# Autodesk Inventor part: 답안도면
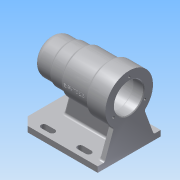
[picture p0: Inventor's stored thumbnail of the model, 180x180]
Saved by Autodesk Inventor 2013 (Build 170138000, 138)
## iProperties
Created: 2017-09
Part Number: 답안도면
Material: 알루미늄 6061
Document SubType Name: Modeling
Designer: Administrator
Density: 2.71 g/cm^3
Mass: 698.012 g
Surface Area: 708.878 cm^2
Volume: 257.569 cm^3
Author: Administrator
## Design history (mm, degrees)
sketch "스케치1"
  geometry: L1 (-56, 0)-(56, 0); L2 (-56, 0)-(-56, 25); L3 (-56, 25)-(-31, 25); L4 (-31, 25)-(-31, 27); L5 (-31, 27)-(-11, 27); L6 (-11, 27)-(-11, 30); L7 (-11, 30)-(28, 30); L8 (28, 30)-(28, 34); L9 (28, 34)-(56, 34); L10 (56, 34)-(56, 21); L11 (56, 21)-(41, 21); L12 (41, 21)-(41, 21); L13 (-13, 21)-(-13, 21); L14 (-13, 21)-(-24.7, 21); L15 (-25, 20.7)-(-25, 17.5); L16 (-25, 17.5)-(-42.7, 17.5); L17 (-43, 17.2)-(-43, 16); L18 (-43, 16)-(-46.7, 16); L19 (-47, 15.7)-(-47, 10.5); L20 (-47, 10.5)-(-47, 10.5); L21 (-50, 7.5)-(-50, 0); L22 (-10, 24)-(38, 24); A1 r 0.3 centre (-46.7, 15.7) between (-46.7, 16) and (-47, 15.7); A2 r 0.3 centre (-42.7, 17.2) between (-42.7, 17.5) and (-43, 17.2); A3 r 0.3 centre (-24.7, 20.7) between (-24.7, 21) and (-25, 20.7); A4 r 3 centre (-10, 21) between (-10, 24) and (-13, 21); A5 r 3 centre (38, 21) between (41, 21) and (38, 24); A6 r 3 centre (-47, 7.5) between (-47, 10.5) and (-50, 7.5); 7 further points
  constraints: 44 end point, 13 parallel, 13 point on line, 12 point on circle, 12 tangent, 6 centre point, 6 perpendicular, 4 equal radius, 1 horizontal, 1 midpoint, 1 vertical alignment
  dimensions: "d0" = 56 distance of L1.start point (0, 0); "d1" = 112 distance of L1.start L1.end; "d2" = 50 diameter of L3 L1; "d3" = 54 diameter of L5 L1; "d4" = 60 diameter of L7 L1; "d5" = 21 diameter of L20 L1; "d6" = 32 diameter of L18 L1; "d7" = 68 diameter of L9 L1; "d8" = 35 diameter of L16 L1; "d9" = 42 diameter of L14 L1; "d10" = 48 diameter of L22 L1; "d11" = 42 diameter of L11 L1; "d12" = 3 distance between parallel lines of L19 L21; "d13" = 4 distance between parallel lines of L17 L19; "d14" = 18 distance between parallel lines of L15 L17; "d15" = 12 distance between parallel lines of L15 L13; "d16" = 54 distance between parallel lines of L12 L13; "d17" = 15 distance between parallel lines of L10 L12; "d18" = 25 distance between parallel lines of L4 L2; "d19" = 45 distance between parallel lines of L6 L2; "d20" = 84 distance between parallel lines of L8 L2; "d22" = 0.3 radius of A1; "d23" = 3 radius of A4
revolve "회전1" sketch "스케치1" stored, may be unused: angle "d21" = 90 deg
sketch "스케치2"
  geometry: L1 (-45, -62)-(45, -62); L2 (45, -62)-(45, -70); L3 (45, -70)-(-45, -70); L4 (-45, -70)-(-45, -62); C1 r 21 at (0, 0) reference; 1 further point
  constraints: 8 end point, 2 parallel, 1 horizontal, 1 midpoint, 1 perpendicular, 1 vertical alignment
  dimensions: "d24" = 90 distance between parallel lines of L2 L4; "d26" = 8 distance between parallel lines of L3 L1; "d27" = 70 distance from line of C1.centre L3
extrude "돌출1" join sketch "스케치2" distance "d28" = 112; taper "d29" = 0 deg
sketch "스케치3"
  geometry: L1 (-112, 0)-(-112, 90) reference; L2 (-77, 49)-(0, 49); L3 (0, 49)-(0, 41); L4 (0, 41)-(-77, 41); L5 (-77, 41)-(-77, 49); L6 (0, 90)-(0, 0) reference; 3 further points
  constraints: 8 end point, 2 horizontal alignment, 2 parallel, 1 horizontal, 1 midpoint, 1 perpendicular, 1 vertical alignment
  dimensions: "d30" = 8 distance between parallel lines of L4 L2; "d34" = 35 distance between parallel lines of L1 L5
extrude "돌출2" join sketch "스케치3" stored distance "d35" = 112; taper "d36" = 0 deg
sketch "스케치8"
  geometry: L1 (56, -62)-(-56, -62) reference; L2 (-21, -62)-(-21, -26.702) reference; L3 (-31, -27)-(-21, -27) reference; L4 (-34, -62)-(-24.622, -27); L5 (-56, -62)-(-56, -70) reference; L6 (-23.818, -24)-(-24.622, -27); L7 (-23.818, -24)-(-21, -24); L8 (-21, -27)-(-21, -24); 1 further point
  constraints: 8 end point, 2 perpendicular, 2 point on line, 1 collinear
  dimensions: "d66" = 22 distance from line of L5 L4.start; "d67" = 105 deg angle of L1 L4; "d68" = 3 distance between parallel lines of L3 L7
extrude "돌출6" join sketch "스케치8" stored distance "d69" = 8; taper "d70" = 0 deg
sketch "스케치4"
  geometry: L1 (41, 8)-(41, 36.236) reference; L2 (0, 8)-(41, 8) reference; L3 (0, 0)-(0, 8) reference; L4 (90, 8)-(90, 0) reference; L5 (49, 8)-(90, 8) reference; L6 (23.1, 43.992)-(10, 8); L7 (66.9, 43.992)-(80, 8); L8 (49, 8)-(49, 36.236) reference; L9 (49, 36.236)-(49, 8); L10 (80, 8)-(49, 8); A1 r 34 centre (45, 70) between (49, 36.236) and (41, 36.236) reference
  constraints: 8 end point, 2 point on circle, 2 point on line, 1 collinear, 1 perpendicular
  dimensions: "d37" = 10 distance from line of L4 L7.end; "d38" = 10 distance from line of L3 L6.end; "d39" = 110 deg angle of L2 L6; "d40" = 110 deg angle of L7 L5
extrude "돌출3" join sketch "스케치4" distance "d41" = 8; taper "d42" = 0 deg
extrude "돌출4" join sketch "스케치4" distance "d43" = 8; taper "d44" = 0 deg
chamfer "모따기1" distance "d45" = 12; stored, may be unused: second distance "d46" = 2, angle "d47" = 45 deg
sketch "스케치5"
  geometry: L1 (77, 39)-(77, 49) reference; L2 (77, 49)-(-23, 49) reference; L3 (-35, -29)-(-35, 37) reference; L4 (41, 42)-(53, 42); L5 (53, 34)-(41, 34); L6 (-11, 42)-(1, 42); L7 (1, 34)-(-11, 34); L8 (41, -26)-(53, -26); L9 (53, -34)-(41, -34); L10 (-11, -26)-(1, -26); L11 (1, -34)-(-11, -34); A1 r 4 centre (53, 38) between (53, 34) and (53, 42); A2 r 4 centre (41, 38) between (41, 42) and (41, 34); A3 r 4 centre (-11, 38) between (-11, 42) and (-11, 34); A4 r 4 centre (1, 38) between (1, 34) and (1, 42); A5 r 4 centre (41, -30) between (41, -26) and (41, -34); A6 r 4 centre (53, -30) between (53, -34) and (53, -26); A7 r 4 centre (-11, -30) between (-11, -26) and (-11, -34); A8 r 4 centre (1, -30) between (1, -34) and (1, -26); 1 further point
  constraints: 16 end point, 16 point on circle, 8 centre point, 4 tangent, 1 horizontal, 1 parallel, 1 perpendicular, 1 vertical, 30 other
  dimensions: "d48" = 12 distance of A1.centre A2.centre; "d50" = 8 distance between parallel lines of L5 L4; "d51" = 34 vertical distance of point (21, 4) A2.centre; "d52" = 24 distance from line of A1.centre L1; "d55" = 52 distance of A2.centre A3.centre; "d58" = 68 distance of A2.centre A5.centre
extrude "돌출5" cut sketch "스케치5" stored distance "d61" = 8; taper "d62" = 0 deg
node "작업 평면1"
sketch "스케치6"
  geometry: L1 (47.5, -26.008)-(47.5, 34) reference; 2 further points
  constraints: 1 horizontal alignment, 1 other
  dimensions: "d63" = 48 distance from line of point (-0.5, 0) L1
feature "엠보싱1" sketch "스케치6" dims "d19" = 45, "d64" = 0.5, "d65" = 0
fillet "모깎기1" dims "d71" = 9, "d72" = 3
fillet "모깎기2" dims "d73" = 3
sketch "스케치9" dims "d76" = 52
  geometry: C1 r 21 at (45, 70) reference; A1 r 34 centre (45, 70) between (68.353, 45.289) and (21.647, 45.289) reference; 6 further points
  constraints: 2 vertical alignment, 1 coincident, 6 other
  dimensions: "d80" = 360 deg dimension on A1.centre point (45, 96) (derived)
hole "구멍1" sketch "스케치9" at (45, 96), (22.483, 57), (67.517, 57) diameter "d82" = 3.242; stored, may be unused: countersink angle "d86" = 90 deg, drill point angle "d88" = 118 deg; dims "d83" = 8, "d84" = 4, "d85" = 2, "d87" = 11
chamfer "모따기2" distance "d89" = 1; stored, may be unused: second distance "d90" = 2, angle "d91" = 45 deg
node "솔리드1"
